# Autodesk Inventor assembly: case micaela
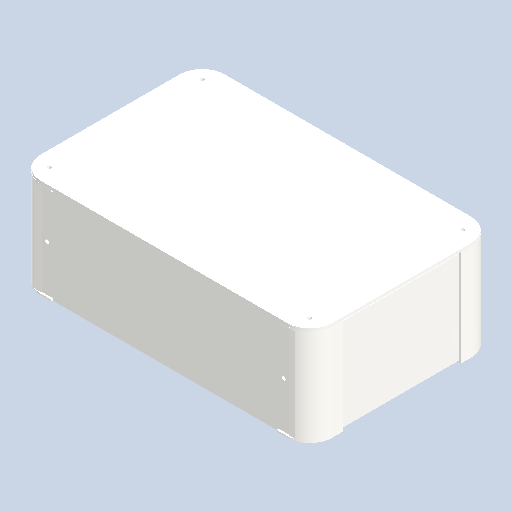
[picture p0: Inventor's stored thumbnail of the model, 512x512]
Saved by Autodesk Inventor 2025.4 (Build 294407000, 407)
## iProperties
Created: 2026-06
Part Number: case micaela
Document SubType Name: Assembly
Designer: AdminForWorker
Title: case micaela v4
Author: AdminForWorker
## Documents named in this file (20)
- c:\worker\convert-fusion-r03-cosv3\tmp\job-1\47\temp\files\c452353c-f839-4329-ab33-f42815f0ce37\5b7afef8-f458-4380-8083-a265f18da46b.iam
- c:\worker\convert-fusion-r03-cosv3\tmp\job-1\47\temp\files\c452353c-f839-4329-ab33-f42815f0ce37\Component2.ipt
- c:\worker\convert-fusion-r03-cosv3\tmp\job-1\47\temp\files\c452353c-f839-4329-ab33-f42815f0ce37\Component3.ipt
- c:\worker\convert-fusion-r03-cosv3\tmp\job-1\47\temp\files\c452353c-f839-4329-ab33-f42815f0ce37\Component4.ipt
- c:\worker\convert-fusion-r03-cosv3\tmp\job-1\47\temp\files\c452353c-f839-4329-ab33-f42815f0ce37\esquina (1) (1) (1) (1) (1).ipt
- c:\worker\convert-fusion-r03-cosv3\tmp\job-1\47\temp\files\c452353c-f839-4329-ab33-f42815f0ce37\esquina (1) (1) (1) (2).ipt
- c:\worker\convert-fusion-r03-cosv3\tmp\job-1\47\temp\files\c452353c-f839-4329-ab33-f42815f0ce37\Component7.ipt
- c:\worker\convert-fusion-r03-cosv3\tmp\job-1\47\temp\files\c452353c-f839-4329-ab33-f42815f0ce37\Component8.ipt
- c:\worker\convert-fusion-r03-cosv3\tmp\job-1\47\temp\files\c452353c-f839-4329-ab33-f42815f0ce37\Component10.ipt
- c:\worker\convert-fusion-r03-cosv3\tmp\job-1\47\temp\files\c452353c-f839-4329-ab33-f42815f0ce37\esquina (1) (1).ipt
- c:\worker\convert-fusion-r03-cosv3\tmp\job-1\47\temp\files\c452353c-f839-4329-ab33-f42815f0ce37\Component14.ipt
- c:\worker\convert-fusion-r03-cosv3\tmp\job-1\47\temp\files\c452353c-f839-4329-ab33-f42815f0ce37\esquina.ipt
- c:\worker\convert-fusion-r03-cosv3\tmp\job-1\47\temp\files\c452353c-f839-4329-ab33-f42815f0ce37\Component16.ipt
- c:\worker\convert-fusion-r03-cosv3\tmp\job-1\47\temp\files\c452353c-f839-4329-ab33-f42815f0ce37\Component17.ipt
- c:\worker\convert-fusion-r03-cosv3\tmp\job-1\47\temp\files\c452353c-f839-4329-ab33-f42815f0ce37\Component18.ipt
- c:\worker\convert-fusion-r03-cosv3\tmp\job-1\47\temp\files\c452353c-f839-4329-ab33-f42815f0ce37\techo.ipt
- c:\worker\convert-fusion-r03-cosv3\tmp\job-1\47\temp\files\c452353c-f839-4329-ab33-f42815f0ce37\Component21.ipt
- c:\worker\convert-fusion-r03-cosv3\tmp\job-1\47\temp\files\c452353c-f839-4329-ab33-f42815f0ce37\Component22.ipt
- c:\worker\convert-fusion-r03-cosv3\tmp\job-1\47\temp\files\c452353c-f839-4329-ab33-f42815f0ce37\Component23.ipt
- c:\worker\convert-fusion-r03-cosv3\tmp\job-1\47\temp\files\c452353c-f839-4329-ab33-f42815f0ce37\Component24.ipt
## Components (19 placed, 19 different names)
1. Component2:1
2. Component3:1
3. Component4:1
4. esquina (1) (1) (1) (1) (1):1
5. esquina (1) (1) (1) (2):1
6. Component7:1
7. Component8:1
8. Component10:1
9. esquina (1) (1):1
10. Component14:1
11. esquina:1
12. Component16:1
13. Component17:1
14. Component18:1
15. techo:1
16. Component21:1
17. Component22:1
18. Component23:1
19. Component24:1
